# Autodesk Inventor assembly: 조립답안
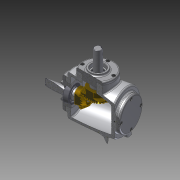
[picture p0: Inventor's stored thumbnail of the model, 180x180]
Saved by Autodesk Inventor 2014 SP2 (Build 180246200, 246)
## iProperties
Created: 2015-01
Part Number: 조립답안
Document SubType Name: Assembly
Designer: 201-07
Author: 201-07
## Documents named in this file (14)
- C:\Users\201-07\Desktop\450105V1016\조립답안.iam
- C:\Users\201-07\Desktop\450105V1016\1-본체.ipt
- C:\Users\201-07\Desktop\450105V1016\커버.ipt
- C:\Users\201-07\Desktop\450105V1016\커버2.ipt
- C:\Users\201-07\Desktop\450105V1016\메인 베벨기어.ipt
- C:\Users\201-07\Desktop\450105V1016\메인 축.ipt
- 메인 축.ipt
- C:\Users\201-07\Desktop\450105V1016\서브 베벨기어.ipt
- C:\Users\201-07\Desktop\450105V1016\서브 축.ipt
- 서브 축.ipt
- C:\Users\201-07\Desktop\450105V1016\베어링 6203.ipt
- C:\Users\201-07\Desktop\450105V1016\키 5x5.ipt
- C:\Users\201-07\Desktop\450105V1016\키 4x4.ipt
- C:\Users\201-07\Desktop\450105V1016\M4.ipt
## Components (13 placed, 2 different names)
1. 1-본체:1
2. M4:1
3. M4:2
4. M4:3
5. M4:4
6. M4:6
7. M4:7
8. M4:8
9. M4:9
10. M4:5
11. M4:10
12. M4:11
13. M4:12
